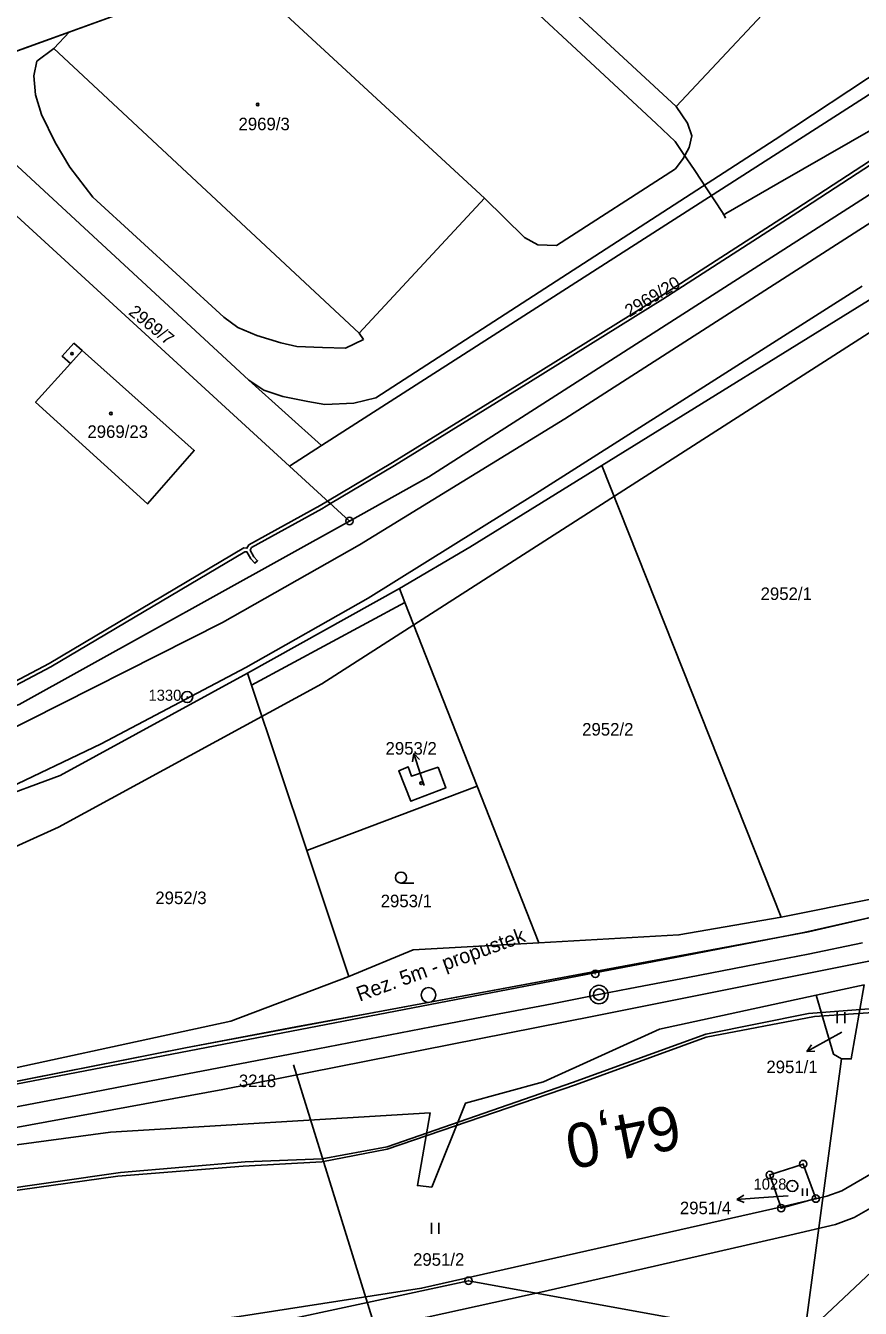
# Model space of a CAD drawing. Extents: x -620552 to -620056, y -1123312 to -1122890.
# Drawn here: x -620409.1 to -620295.9, y -1123151.7 to -1122977.8 of the extents above; entities that cross this region are included whole.
import ezdxf

# ---------------------------------------------------------------- set-up
doc = ezdxf.new("R2010")
doc.units = 0
for name, color, linetype in [('CETIN', 7, 'Continuous'), ('HranDP', 7, 'Continuous'), ('Hranice parcel', 7, 'Continuous'), ('Parcelní čísla', 7, 'Continuous'), ('Pop  PČ popisy', 7, 'Continuous'), ('PS 06-14-01_trasa_sdělovací_nové', 7, 'Continuous'), ('Rámečky', 7, 'Continuous'), ('Rámečky-tisk', 7, 'Continuous'), ('SSZT', 7, 'Continuous'), ('SSZT-DK', 7, 'Continuous'), ('SSZT-TK', 7, 'Continuous'), ('VAS vodovod', 7, 'Continuous'), ('Vnitřní kresba', 7, 'Continuous'), ('Vrstva 1', 7, 'Continuous'), ('Vrstva 13', 7, 'Continuous'), ('Vrstva 19', 7, 'Continuous'), ('Vrstva 3', 7, 'Continuous'), ('Vrstva 7', 7, 'Continuous'), ('Věcná břemena k části', 7, 'Continuous'), ('Značky bodu BP', 7, 'Continuous'), ('Značky budov', 7, 'Continuous'), ('Značky kultur', 7, 'Continuous'), ('ČD-T', 7, 'Continuous')]:
    doc.layers.add(name, color=color, linetype=linetype)

msp = doc.modelspace()

# ---------------------------------------------------------------- linework, layer by layer
at = {"layer": 'CETIN'}
msp.add_lwpolyline([(-620523.51, -1123111.55), (-620453.59, -1123102.46), (-620423.24, -1123094.92), (-620404.67, -1123086.51), (-620368.95, -1123067.06), (-620277.61, -1123008.49), (-620145.62, -1122921.55)], dxfattribs=at)
at = {"layer": 'HranDP'}
for p, q in [((-620306.69, -1123098.69), (-620294.3, -1123096.22)), ((-620301.93, -1123109.26), (-620295.45, -1123107.86))]:
    msp.add_line(p, q, dxfattribs=at)
for points in [[(-620339.56, -1123102.2), (-620320.55, -1123101.1), (-620306.69, -1123098.69)], [(-620339.56, -1123102.2), (-620356.6, -1123103.13), (-620365.33, -1123106.73)], [(-620420.55, -1123121.3), (-620381.33, -1123112.8), (-620365.33, -1123106.73)], [(-620301.93, -1123109.26), (-620323.18, -1123113.87), (-620338.92, -1123121.01), (-620349.51, -1123123.93), (-620354.07, -1123135.32), (-620356.01, -1123135.09), (-620354.3, -1123125.25), (-620397.61, -1123127.84), (-620420.8, -1123130.97)]]:
    msp.add_lwpolyline(points, dxfattribs=at)
at = {"layer": 'Hranice parcel'}
for p, q in [((-620369, -1123034.76), (-620282.4, -1122979.23)), ((-620373.35, -1123037.54), (-620421.73, -1122993.23)), ((-620289.02, -1123011.5), (-620330.98, -1123037.45)), ((-620373.35, -1123037.54), (-620369, -1123034.76)), ((-620330.98, -1123037.45), (-620306.69, -1123098.69)), ((-620365.22, -1123044.99), (-620373.35, -1123037.54)), ((-620358.43, -1123054.16), (-620379.05, -1123065.63)), ((-620306.69, -1123098.69), (-620294.3, -1123096.22)), ((-620301.93, -1123109.26), (-620295.45, -1123107.86)), ((-620303.5, -1123155.32), (-620298.49, -1123117.9))]:
    msp.add_line(p, q, dxfattribs=at)
for points in [[(-620325.34, -1122950.49), (-620303.81, -1122970.47), (-620320.91, -1122988.8), (-620351.92, -1122960.11)], [(-620380.28, -1122970.38), (-620346.89, -1123001.2)], [(-620346.89, -1123001.2), (-620363.9, -1123019.53), (-620405.31, -1122980.94), (-620403.21, -1122978.69)], [(-620419.67, -1122988.35), (-620410.26, -1122996.87), (-620378.87, -1123025.88), (-620369, -1123034.76)], [(-620365.22, -1123044.99), (-620354.45, -1123039), (-620287.33, -1122996.04)], [(-620402.6, -1123020.87), (-620401.48, -1123021.87), (-620386.27, -1123035.43), (-620392.63, -1123042.68), (-620407.79, -1123028.9), (-620403.06, -1123023.63), (-620404.19, -1123022.62), (-620402.6, -1123020.87)], [(-620330.98, -1123037.45), (-620348.88, -1123048.53), (-620358.43, -1123054.16)], [(-620448.18, -1123082.73), (-620410.01, -1123069.89), (-620365.22, -1123044.99)], [(-620358.43, -1123054.16), (-620357.7, -1123056.02), (-620347.91, -1123080.94), (-620339.56, -1123102.2)], [(-620379.05, -1123065.63), (-620404.47, -1123079.48), (-620414.05, -1123083.02)], [(-620365.33, -1123106.73), (-620371.02, -1123089.67), (-620378.51, -1123067.23), (-620379.05, -1123065.63)], [(-620353.21, -1123078.36), (-620352.17, -1123081.18), (-620356.92, -1123082.98), (-620358.53, -1123078.86), (-620357.25, -1123078.34), (-620356.83, -1123079.58), (-620353.21, -1123078.36)], [(-620339.56, -1123102.2), (-620320.55, -1123101.1), (-620306.69, -1123098.69)], [(-620339.56, -1123102.2), (-620356.6, -1123103.13), (-620365.33, -1123106.73)], [(-620267.31, -1123105.13), (-620271.09, -1123121.69), (-620283, -1123136.04), (-620303.5, -1123155.32)], [(-620420.55, -1123121.3), (-620381.33, -1123112.8), (-620365.33, -1123106.73)], [(-620298.49, -1123117.9), (-620297.19, -1123117.91), (-620295.45, -1123107.86)], [(-620301.93, -1123109.26), (-620323.18, -1123113.87), (-620338.92, -1123121.01), (-620349.51, -1123123.93), (-620354.07, -1123135.32), (-620356.01, -1123135.09), (-620354.3, -1123125.25), (-620397.61, -1123127.84), (-620420.8, -1123130.97)], [(-620298.49, -1123117.9), (-620299.58, -1123117.29), (-620301.93, -1123109.26)], [(-620301.98, -1123136.86), (-620306.69, -1123138.15), (-620308.23, -1123133.65), (-620303.71, -1123132.17), (-620301.98, -1123136.86)], [(-620390.82, -1123156.97), (-620349.09, -1123147.99), (-620304.63, -1123156.08), (-620303.63, -1123156.28)]]:
    msp.add_lwpolyline(points, dxfattribs=at)
at = {"layer": 'Pop  PČ popisy'}
for p, q in [((-620356.5, -1123076.52), (-620356.66, -1123077.62)), ((-620355.57, -1123079.37), (-620356.5, -1123076.52)), ((-620356.5, -1123076.52), (-620355.71, -1123077.31)), ((-620355.09, -1123080.85), (-620355.57, -1123079.37)), ((-620300.59, -1123115.47), (-620303.21, -1123116.93)), ((-620298.45, -1123114.27), (-620300.59, -1123115.47)), ((-620303.21, -1123116.93), (-620302.58, -1123116)), ((-620303.21, -1123116.93), (-620302.1, -1123116.88)), ((-620312.71, -1123136.97), (-620311.75, -1123136.4)), ((-620305.74, -1123136.49), (-620309.72, -1123136.76)), ((-620309.72, -1123136.76), (-620312.71, -1123136.97)), ((-620312.71, -1123136.97), (-620311.68, -1123137.4))]:
    msp.add_line(p, q, dxfattribs=at)
at = {"layer": 'PS 06-14-01_trasa_sdělovací_nové'}
msp.add_lwpolyline([(-620490.54, -1123135.38), (-620469.22, -1123131.24), (-620467.69, -1123132.26), (-620427.58, -1123124.35), (-620387.47, -1123116.43), (-620361.88, -1123111.62), (-620332.44, -1123106.16), (-620302.99, -1123100.7), (-620292.4, -1123098.24)], dxfattribs=at)
at = {"layer": 'Rámečky'}
msp.add_line((-620157.19, -1122889.6), (-620552.1, -1123032.6), dxfattribs=at)
at = {"layer": 'Rámečky-tisk'}
msp.add_lwpolyline([(-620450.98, -1123311.85), (-620056.07, -1123168.86), (-620157.19, -1122889.6), (-620552.1, -1123032.6)], dxfattribs=at)
at = {"layer": 'SSZT'}
msp.add_lwpolyline([(-620166.88, -1123010.24), (-620171.39, -1123017.17), (-620176.01, -1123023.63), (-620178.84, -1123027.27), (-620187.42, -1123037.54), (-620200.37, -1123050.67), (-620210.46, -1123059.35), (-620223.07, -1123068.67), (-620236.68, -1123077.14), (-620256.88, -1123087.09), (-620270.91, -1123092.6), (-620285.4, -1123096.67), (-620303.6, -1123100.76), (-620319.9, -1123103.93), (-620331.96, -1123106.25), (-620430.51, -1123125.18), (-620444.41, -1123127.82), (-620476.1, -1123133.9), (-620498.92, -1123138.28), (-620512.26, -1123140.83), (-620512.86, -1123140.95)], dxfattribs=at)
at = {"layer": 'SSZT-DK'}
msp.add_lwpolyline([(-620291.83, -1123110.91), (-620302.99, -1123111.77), (-620316.91, -1123114.57), (-620334.97, -1123121.13), (-620360.11, -1123129.84), (-620368.91, -1123131.45), (-620379.35, -1123131.87), (-620396.27, -1123133.31), (-620414.27, -1123135.89), (-620422.75, -1123137.39), (-620436.53, -1123139.54), (-620485.74, -1123145.76), (-620509.46, -1123150.35)], dxfattribs=at)
at = {"layer": 'SSZT-TK'}
msp.add_lwpolyline([(-620135.22, -1122950.28), (-620135.4, -1122951.34), (-620146.6, -1122984.04), (-620155.29, -1123003.62), (-620165.83, -1123021.36), (-620186.83, -1123047.79), (-620210, -1123069.75), (-620240.2, -1123085.98), (-620267.98, -1123097.08), (-620292.31, -1123104.15), (-620332.1, -1123112.12), (-620382.38, -1123122.06), (-620466.84, -1123137.57), (-620511.01, -1123146.08)], dxfattribs=at)
at = {"layer": 'VAS vodovod'}
for points in [[(-620260.52, -1122971.14), (-620273.97, -1122979.53), (-620287.42, -1122987.93), (-620297.29, -1122993.57), (-620307.15, -1122999.21), (-620314.18, -1123003.29), (-620314.33, -1123003.39), (-620314.47, -1123003.48), (-620314.66, -1123003.17), (-620315.7, -1123001.56), (-620316.76, -1122999.96), (-620318.4, -1122997.49), (-620320.04, -1122995.03), (-620321.07, -1122993.52), (-620323.65, -1122991.1), (-620326.23, -1122988.68), (-620330.65, -1122984.59), (-620335.07, -1122980.5), (-620339.44, -1122976.42), (-620343.82, -1122972.33), (-620352.52, -1122964.33), (-620355.63, -1122961.46)], [(-620314.47, -1123003.48), (-620314.34, -1123003.71), (-620314.21, -1123003.93)], [(-620149.01, -1123008.86), (-620153.26, -1123021.35), (-620170.32, -1123042.17), (-620174.28, -1123046.08), (-620197.72, -1123068.73), (-620228.79, -1123097.03), (-620270.23, -1123119.97), (-620279.98, -1123125.39), (-620293.71, -1123133.06), (-620298.47, -1123135.79), (-620300.47, -1123136.51), (-620304.69, -1123137.51), (-620306.42, -1123137.92), (-620355.45, -1123149.02), (-620380.2, -1123152.84), (-620387.1, -1123153.74), (-620431.25, -1123159.48), (-620484.75, -1123167.02), (-620502.03, -1123170.86)], [(-620143.62, -1123010.63), (-620143.76, -1123012.48), (-620147.75, -1123024.43), (-620148.88, -1123025.86), (-620151.68, -1123028.7), (-620167.48, -1123044.99), (-620171.49, -1123048.94), (-620194.98, -1123071.65), (-620226.44, -1123100.3), (-620258.1, -1123117.83), (-620268.29, -1123123.47), (-620278.03, -1123128.88), (-620291.74, -1123136.54), (-620296.78, -1123139.43), (-620299.32, -1123140.35), (-620305.52, -1123141.82), (-620338.85, -1123149.47), (-620354.7, -1123152.95), (-620379.64, -1123156.8), (-620430.73, -1123163.45), (-620484.29, -1123170.42), (-620500.86, -1123174.1)]]:
    msp.add_lwpolyline(points, dxfattribs=at)
at = {"layer": 'Vnitřní kresba'}
for p, q in [((-620405.31, -1122980.94), (-620407.63, -1122982.63)), ((-620407.63, -1122982.63), (-620408.01, -1122984.62)), ((-620307.51, -1122993.27), (-620292.44, -1122983.33)), ((-620408.01, -1122984.62), (-620407.79, -1122987.2)), ((-620407.79, -1122987.2), (-620406.97, -1122989.87)), ((-620406.97, -1122989.87), (-620405.11, -1122993.68)), ((-620320.91, -1122988.8), (-620319.39, -1122991.07)), ((-620319.39, -1122991.07), (-620318.78, -1122992.75)), ((-620405.11, -1122993.68), (-620403.13, -1122997.02)), ((-620361.67, -1123028.28), (-620307.51, -1122993.27)), ((-620318.78, -1122992.75), (-620319.15, -1122994.37)), ((-620319.15, -1122994.37), (-620319.98, -1122995.84)), ((-620403.13, -1122997.02), (-620400.01, -1123001.09)), ((-620320.99, -1122997.25), (-620337.13, -1123007.62)), ((-620319.98, -1122995.84), (-620320.99, -1122997.25)), ((-620336.04, -1123031.13), (-620285.65, -1122998.79)), ((-620400.01, -1123001.09), (-620382.25, -1123017.34)), ((-620341.49, -1123006.57), (-620346.89, -1123001.2)), ((-620339.7, -1123007.56), (-620341.49, -1123006.57)), ((-620337.13, -1123007.62), (-620339.7, -1123007.56)), ((-620339.98, -1123041.29), (-620295.72, -1123013.16)), ((-620382.25, -1123017.34), (-620380.35, -1123018.75)), ((-620380.35, -1123018.75), (-620377.77, -1123019.86)), ((-620377.77, -1123019.86), (-620374.53, -1123020.83)), ((-620363.32, -1123020.4), (-620363.9, -1123019.53)), ((-620374.53, -1123020.83), (-620372.37, -1123021.35)), ((-620372.37, -1123021.35), (-620368.87, -1123021.48)), ((-620368.87, -1123021.48), (-620365.77, -1123021.56)), ((-620365.77, -1123021.56), (-620363.32, -1123020.4)), ((-620403.06, -1123023.63), (-620401.48, -1123021.87)), ((-620376.83, -1123027.23), (-620378.87, -1123025.88)), ((-620376.83, -1123027.23), (-620374.25, -1123028.1)), ((-620374.25, -1123028.1), (-620370.88, -1123028.79)), ((-620364.63, -1123029), (-620361.67, -1123028.28)), ((-620370.88, -1123028.79), (-620368.56, -1123029.21)), ((-620368.56, -1123029.21), (-620364.63, -1123029)), ((-620363.85, -1123048.22), (-620336.04, -1123031.13)), ((-620362.71, -1123055.46), (-620339.98, -1123041.29)), ((-620382.46, -1123058.76), (-620363.85, -1123048.22)), ((-620379.28, -1123064.86), (-620362.71, -1123055.46)), ((-620357.7, -1123056.02), (-620378.51, -1123067.23)), ((-620415.29, -1123075.34), (-620382.46, -1123058.76)), ((-620398.9, -1123075.2), (-620379.28, -1123064.86)), ((-620412.3, -1123081.62), (-620398.9, -1123075.2)), ((-620371.02, -1123089.67), (-620347.91, -1123080.94))]:
    msp.add_line(p, q, dxfattribs=at)
at = {"layer": 'Vrstva 1'}
for points in [[(-620490.54, -1123135.38), (-620469.22, -1123131.24), (-620467.69, -1123132.26), (-620387.47, -1123116.43), (-620372.49, -1123113.59), (-620361.88, -1123111.62), (-620302.99, -1123100.7), (-620292.4, -1123098.24)], [(-620295.67, -1123102.19), (-620303.02, -1123103.7), (-620311.43, -1123105.36), (-620319.33, -1123106.87), (-620327.2, -1123108.39), (-620331.39, -1123109.19), (-620337.74, -1123110.43), (-620345.88, -1123111.99), (-620354.1, -1123113.57), (-620362.49, -1123115.18), (-620370.92, -1123116.8), (-620378.91, -1123118.34), (-620387.17, -1123119.94), (-620395.12, -1123121.47), (-620403.3, -1123123.04), (-620411.59, -1123124.63)]]:
    msp.add_lwpolyline(points, dxfattribs=at)
at = {"layer": 'Vrstva 13'}
msp.add_circle((-620354.51, -1123109.25), 1, dxfattribs=at)
at = {"layer": 'Vrstva 19'}
msp.add_line((-620355.01, -1123176.04), (-620372.81, -1123118.74), dxfattribs=at)
at = {"layer": 'Vrstva 7'}
msp.add_line((-620331.84, -1123106.38), (-620331.94, -1123106.4), dxfattribs=at)
for centre, radius in [((-620331.89, -1123106.39), 0.5), ((-620331.39, -1123109.19), 1.25), ((-620331.39, -1123109.19), 0.752)]:
    msp.add_circle(centre, radius, dxfattribs=at)
at = {"layer": 'Věcná břemena k části'}
msp.add_lwpolyline([(-620359.12, -1123037.46), (-620340.69, -1123026.08), (-620322.75, -1123014.93), (-620304.43, -1123003.11), (-620287.42, -1122992.06), (-620285.83, -1122990.94), (-620285.6, -1122990.17), (-620287.7, -1122991.64), (-620304.71, -1123002.69), (-620323.01, -1123014.51), (-620340.95, -1123025.66), (-620359.38, -1123037.04), (-620368.18, -1123042.28), (-620367.79, -1123042.63)], close=True, dxfattribs=at)
msp.add_lwpolyline([(-620411.29, -1123067.69), (-620405.72, -1123064.74), (-620379.41, -1123049.16), (-620379.14, -1123049.19), (-620378.61, -1123050.13), (-620378.05, -1123050.72), (-620377.69, -1123050.38), (-620378.21, -1123049.83), (-620378.69, -1123048.95), (-620378.5, -1123048.59), (-620368.96, -1123043.33), (-620367.79, -1123042.63), (-620368.18, -1123042.28), (-620369.2, -1123042.89), (-620378.86, -1123048.23), (-620379.12, -1123048.68), (-620379.53, -1123048.64), (-620405.96, -1123064.3), (-620411.49, -1123067.23)], dxfattribs=at)
at = {"layer": 'Značky bodu BP'}
for centre, radius in [((-620365.22, -1123044.99), 0.5), ((-620365.22, -1123044.99), 0.0303), ((-620387.23, -1123068.86), 0.75), ((-620387.23, -1123068.86), 0.03), ((-620303.71, -1123132.17), 0.5), ((-620303.71, -1123132.17), 0.0303), ((-620308.23, -1123133.65), 0.5), ((-620308.23, -1123133.65), 0.0303), ((-620305.18, -1123135.14), 0.75), ((-620305.18, -1123135.14), 0.03), ((-620301.98, -1123136.86), 0.5), ((-620306.69, -1123138.15), 0.5), ((-620306.69, -1123138.15), 0.0303), ((-620301.98, -1123136.86), 0.0303), ((-620349.09, -1123147.99), 0.5), ((-620349.09, -1123147.99), 0.0303)]:
    msp.add_circle(centre, radius, dxfattribs=at)
at = {"layer": 'Značky budov'}
for centre in [(-620377.67, -1122988.52), (-620402.85, -1123022.3), (-620397.57, -1123030.41), (-620355.49, -1123080.54)]:
    msp.add_circle(centre, 0.175, dxfattribs=at)
at = {"layer": 'Značky kultur'}
for p, q in [((-620358.24, -1123094.08), (-620356.49, -1123094.08)), ((-620299.07, -1123113.08), (-620299.07, -1123111.58)), ((-620298.07, -1123113.08), (-620298.07, -1123111.58)), ((-620303.81, -1123136.49), (-620303.81, -1123135.49)), ((-620303.14, -1123136.49), (-620303.14, -1123135.49)), ((-620354.1, -1123141.62), (-620354.1, -1123140.12)), ((-620353.1, -1123141.62), (-620353.1, -1123140.12))]:
    msp.add_line(p, q, dxfattribs=at)
msp.add_circle((-620358.24, -1123093.33), 0.75, dxfattribs=at)
at = {"layer": 'ČD-T'}
msp.add_lwpolyline([(-620291.59, -1123111.44), (-620302.16, -1123112.16), (-620316.84, -1123114.96), (-620334.57, -1123121.41), (-620360.1, -1123130.17), (-620368.95, -1123131.86), (-620379.62, -1123132.44), (-620396.63, -1123133.82), (-620414.44, -1123136.3), (-620422.88, -1123137.72), (-620436.71, -1123139.94), (-620485.39, -1123146.38), (-620509.25, -1123150.92)], dxfattribs=at)

# ---------------------------------------------------------------- texts
at = {"layer": 'Parcelní čísla'}
for s, p in [('2969/3', (-620380.27, -1122992.01)), ('2969/23', (-620400.76, -1123033.72)), ('2952/1', (-620309.47, -1123055.7)), ('2952/2', (-620333.67, -1123074.08)), ('2953/2', (-620360.33, -1123076.66)), ('2952/3', (-620391.55, -1123096.93)), ('2953/1', (-620360.99, -1123097.35)), ('2951/1', (-620308.69, -1123119.85)), ('3218', (-620380.22, -1123121.74)), ('2951/4', (-620320.42, -1123138.97)), ('2951/2', (-620356.6, -1123145.96))]:
    msp.add_text(s, height=1.7, dxfattribs=at).set_placement(p)
for s, rotation, p in [('2969/20', 31, (-620327.24, -1123017.4)), ('2969/7', 321, (-620395.29, -1123016.88))]:
    msp.add_text(s, height=1.7, rotation=rotation, dxfattribs=at).set_placement(p)
at = {"layer": 'Vrstva 3'}
msp.add_text('Rez. 5m - propustek', height=2, rotation=19.9058, dxfattribs=at).set_placement((-620363.85, -1123110.16))
at = {"layer": 'Vrstva 7'}
msp.add_text('64,0', height=6, rotation=190.9919, dxfattribs=at).set_placement((-620321, -1123124.05))
at = {"layer": 'Značky bodu BP'}
for s, p in [('1330', (-620392.48, -1123069.36)), ('1028', (-620310.43, -1123135.64))]:
    msp.add_text(s, height=1.5, dxfattribs=at).set_placement(p)

doc.saveas('drawing.dxf')
